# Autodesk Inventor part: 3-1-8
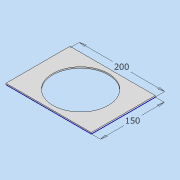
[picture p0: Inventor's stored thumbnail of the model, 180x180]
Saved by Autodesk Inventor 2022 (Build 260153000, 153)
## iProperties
Created: 2021-07
Part Number: 3-1-8
Material: 一般
Document SubType Name: Modeling
Designer: DesignLab
Density: 1 g/cm^3
Appearance: 既定
Author: DesignLab
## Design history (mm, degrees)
sketch "スケッチ1"
  geometry: L1 (0, 0)-(-200, 0); L2 (-200, 0)-(-200, -150); L3 (-200, -150)-(0, -150); L4 (0, -150)-(0, 0)
  constraints: 8 end point, 2 parallel, 1 horizontal, 1 perpendicular
  dimensions: "d0" = 200 distance of L3.end L2.end; "d1" = 150 distance of L2.end L1.end
extrude "押し出し1" new body sketch "スケッチ1" distance "d2" = 3; taper "d3" = 0 deg
sketch "スケッチ2"
  geometry: L1 (200, 150)-(0, 150) reference; L2 (0, 150)-(0, 0) reference; C1 r 65 at (100, 75); 2 further points
  constraints: 2 midpoint, 1 centre point
  dimensions: "d4" = 130 diameter of C1; "d9" = 100 distance from line of C1.centre L2 (= 0.5 x d0); "d10" = 75 distance from line of C1.centre L1 (= 0.5 x d1)
extrude "押し出し2" cut sketch "スケッチ2" distance "d7" = 3; taper "d8" = 0 deg
node "ソリッド1"
